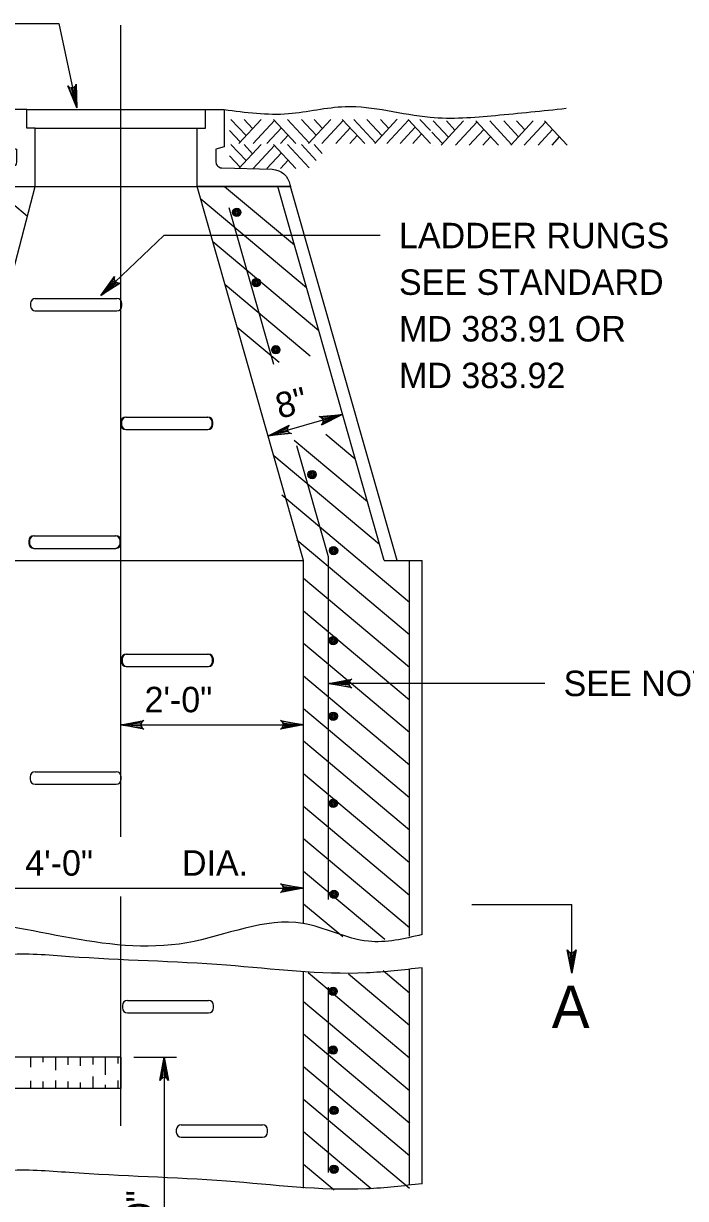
# Model space of a CAD drawing. Extents: x 0.2 to 7.1, y 1.2 to 11.2.
# Drawn here: x 1.727 to 3.289, y 5.546 to 8.317 of the extents above; entities that cross this region are included whole.
import ezdxf

# ---------------------------------------------------------------- set-up
doc = ezdxf.new("R2010")
doc.units = 0
for name, color, linetype in [('DETL-DIMS', 7, 'Continuous'), ('DETL-LINE', 7, 'Continuous'), ('DETL-NOTE', 7, 'Continuous'), ('DETL-PATT', 7, 'Continuous')]:
    doc.layers.add(name, color=color, linetype=linetype)

msp = doc.modelspace()

# ---------------------------------------------------------------- linework, layer by layer
at = {"layer": 'DETL-DIMS'}
for p, q in [((1.6294, 8.3172), (1.8102, 8.3172)), ((1.8102, 8.3172), (1.8527, 8.1187)), ((1.9564, 6.3991), (1.9564, 8.3133)), ((2.0583, 7.8172), (1.9094, 7.6754)), ((2.5686, 7.8172), (2.0583, 7.8172)), ((2.4798, 7.3951), (2.304, 7.3451)), ((2.957, 6.7604), (2.4466, 6.7604)), ((1.9564, 6.6633), (2.3878, 6.6633)), ((1.525, 6.2779), (2.3878, 6.2779)), ((1.9564, 5.7169), (1.9564, 6.2581)), ((2.7848, 6.2393), (3.0201, 6.2393)), ((3.0201, 6.0775), (3.0201, 6.2393)), ((1.9869, 5.879), (2.0881, 5.879)), ((2.0587, 5.879), (2.0587, 5.1333))]:
    msp.add_line(p, q, dxfattribs=at)
for points in [[(1.8527, 8.1187), (1.8312, 8.1701), (1.8349, 8.1666), (1.839, 8.1652), (1.8427, 8.1654), (1.8462, 8.1668), (1.8493, 8.1697), (1.8513, 8.1744), (1.8527, 8.1187), (1.8493, 8.1697), (1.8462, 8.1668), (1.8527, 8.1187), (1.8427, 8.1654), (1.839, 8.1652), (1.8527, 8.1187), (1.8349, 8.1666)], [(1.9094, 7.6754), (1.942, 7.7206), (1.941, 7.7156), (1.9419, 7.7114), (1.944, 7.7083), (1.947, 7.7061), (1.9511, 7.7049), (1.9562, 7.7057), (1.9094, 7.6754), (1.9511, 7.7049), (1.947, 7.7061), (1.9094, 7.6754), (1.944, 7.7083), (1.9419, 7.7114), (1.9094, 7.6754), (1.941, 7.7156)], [(2.4798, 7.3951), (2.4298, 7.3702), (2.4331, 7.3742), (2.4342, 7.3783), (2.4338, 7.382), (2.4322, 7.3854), (2.4291, 7.3883), (2.4242, 7.39), (2.4798, 7.3951), (2.4291, 7.3883), (2.4322, 7.3854), (2.4798, 7.3951), (2.4338, 7.382), (2.4342, 7.3783), (2.4798, 7.3951), (2.4331, 7.3742)], [(2.304, 7.3451), (2.3539, 7.37), (2.3506, 7.366), (2.3496, 7.3619), (2.35, 7.3582), (2.3516, 7.3548), (2.3547, 7.3519), (2.3595, 7.3502), (2.304, 7.3451), (2.3547, 7.3519), (2.3516, 7.3548), (2.304, 7.3451), (2.35, 7.3582), (2.3496, 7.3619), (2.304, 7.3451), (2.3506, 7.366)], [(2.4466, 6.7604), (2.5014, 6.7706), (2.4972, 6.7677), (2.495, 6.764), (2.4944, 6.7604), (2.495, 6.7567), (2.4972, 6.753), (2.5014, 6.7501), (2.4466, 6.7604), (2.4972, 6.753), (2.495, 6.7567), (2.4466, 6.7604), (2.4944, 6.7604), (2.495, 6.764), (2.4466, 6.7604), (2.4972, 6.7677)], [(1.9564, 6.6633), (2.0112, 6.6736), (2.007, 6.6706), (2.0048, 6.667), (2.0042, 6.6633), (2.0048, 6.6596), (2.007, 6.6559), (2.0112, 6.653), (1.9564, 6.6633), (2.007, 6.6559), (2.0048, 6.6596), (1.9564, 6.6633), (2.0042, 6.6633), (2.0048, 6.667), (1.9564, 6.6633), (2.007, 6.6706)], [(2.3878, 6.6633), (2.3329, 6.653), (2.3372, 6.6559), (2.3393, 6.6596), (2.34, 6.6633), (2.3393, 6.667), (2.3372, 6.6706), (2.3329, 6.6736), (2.3878, 6.6633), (2.3372, 6.6706), (2.3393, 6.667), (2.3878, 6.6633), (2.34, 6.6633), (2.3393, 6.6596), (2.3878, 6.6633), (2.3372, 6.6559)], [(2.3878, 6.2779), (2.3329, 6.2677), (2.3372, 6.2706), (2.3393, 6.2743), (2.34, 6.2779), (2.3393, 6.2816), (2.3372, 6.2853), (2.3329, 6.2882), (2.3878, 6.2779), (2.3372, 6.2853), (2.3393, 6.2816), (2.3878, 6.2779), (2.34, 6.2779), (2.3393, 6.2743), (2.3878, 6.2779), (2.3372, 6.2706)], [(3.0201, 6.0775), (3.0098, 6.1324), (3.0128, 6.1281), (3.0164, 6.126), (3.0201, 6.1253), (3.0238, 6.126), (3.0275, 6.1281), (3.0304, 6.1324), (3.0201, 6.0775), (3.0275, 6.1281), (3.0238, 6.126), (3.0201, 6.0775), (3.0201, 6.1253), (3.0164, 6.126), (3.0201, 6.0775), (3.0128, 6.1281)], [(2.0587, 5.879), (2.069, 5.8242), (2.0661, 5.8284), (2.0624, 5.8306), (2.0587, 5.8313), (2.055, 5.8306), (2.0514, 5.8284), (2.0484, 5.8242), (2.0587, 5.879), (2.0514, 5.8284), (2.055, 5.8306), (2.0587, 5.879), (2.0587, 5.8313), (2.0624, 5.8306), (2.0587, 5.879), (2.0661, 5.8284)]]:
    msp.add_lwpolyline(points, dxfattribs=at)
at = {"layer": 'DETL-LINE'}
for p, q in [((1.7346, 8.1145), (2.1562, 8.1145)), ((1.7542, 8.0704), (2.1366, 8.0704)), ((1.525, 7.0508), (1.7542, 7.9331)), ((1.5336, 7.9331), (2.3572, 7.9331)), ((2.3878, 7.0508), (2.1366, 7.9331)), ((2.5778, 7.0508), (2.3266, 7.9331)), ((2.6084, 7.0508), (2.3572, 7.9331)), ((2.3174, 7.5127), (2.2122, 7.8822)), ((1.7437, 7.657), (1.7437, 7.6511)), ((1.7537, 7.6687), (1.9455, 7.6687)), ((1.7555, 7.6687), (1.9473, 7.6687)), ((1.9591, 7.6511), (1.9591, 7.657)), ((1.7537, 7.6393), (1.9455, 7.6393)), ((1.7555, 7.6393), (1.9473, 7.6393)), ((1.9565, 7.377), (1.9565, 7.3711)), ((1.9583, 7.377), (1.9583, 7.3711)), ((1.9683, 7.3887), (2.1601, 7.3887)), ((1.9701, 7.3887), (2.1619, 7.3887)), ((2.1718, 7.3711), (2.1718, 7.377)), ((2.1736, 7.3711), (2.1736, 7.377)), ((1.9683, 7.3593), (2.1601, 7.3593)), ((1.9701, 7.3593), (2.1619, 7.3593)), ((2.4466, 7.059), (2.372, 7.3209)), ((1.7394, 7.097), (1.7394, 7.0911)), ((1.7412, 7.097), (1.7412, 7.0911)), ((1.7512, 7.1088), (1.943, 7.1088)), ((1.753, 7.1088), (1.9448, 7.1088)), ((1.9548, 7.0911), (1.9548, 7.097)), ((1.9565, 7.0911), (1.9565, 7.097)), ((1.7512, 7.0793), (1.943, 7.0793)), ((1.753, 7.0793), (1.9448, 7.0793)), ((1.5642, 7.0508), (2.3878, 7.0508)), ((2.3878, 6.1946), (2.3878, 7.0508)), ((2.4466, 6.2507), (2.4466, 7.059)), ((2.5774, 7.0508), (2.6672, 7.0508)), ((2.6378, 6.1647), (2.6378, 7.0508)), ((2.6672, 6.1684), (2.6672, 7.0508)), ((1.9578, 6.8183), (1.9578, 6.8124)), ((1.9596, 6.8183), (1.9596, 6.8124)), ((1.9695, 6.83), (2.1613, 6.83)), ((1.9713, 6.83), (2.1631, 6.83)), ((2.1731, 6.8124), (2.1731, 6.8183)), ((2.1749, 6.8124), (2.1749, 6.8183)), ((1.9695, 6.8006), (2.1613, 6.8006)), ((1.9713, 6.8006), (2.1631, 6.8006)), ((1.7423, 6.5407), (1.7423, 6.5348)), ((1.7541, 6.5525), (1.9459, 6.5525)), ((1.9576, 6.5348), (1.9576, 6.5407)), ((1.7541, 6.5231), (1.9459, 6.5231)), ((2.3878, 5.5702), (2.3878, 6.0795)), ((2.6378, 5.578), (2.6378, 6.0873)), ((2.6672, 5.5807), (2.6672, 6.09)), ((2.4466, 5.6071), (2.4466, 6.0441)), ((1.9601, 6.0013), (1.9601, 5.9954)), ((1.9719, 6.013), (2.1636, 6.013)), ((2.1754, 5.9954), (2.1754, 6.0013)), ((1.9719, 5.9836), (2.1636, 5.9836)), ((1.9575, 5.879), (1.4624, 5.879)), ((1.9575, 5.8055), (1.9575, 5.879)), ((1.9575, 5.8055), (1.4624, 5.8055)), ((2.0992, 5.7199), (2.291, 5.7199)), ((2.0874, 5.7082), (2.0874, 5.7023)), ((2.0992, 5.6905), (2.291, 5.6905)), ((2.3027, 5.7023), (2.3027, 5.7082))]:
    msp.add_line(p, q, dxfattribs=at)
for points in [[(1.6905, 8.1145), (1.6905, 8.0263), (1.7101, 8.0206), (1.7101, 7.9915), (1.7094, 7.9858), (1.7073, 7.9827), (1.7053, 7.981), (1.7028, 7.9789), (1.6994, 7.9771), (1.6958, 7.9768), (1.5775, 7.9733), (1.5693, 7.9723), (1.5614, 7.9695), (1.5551, 7.9667), (1.5496, 7.9626), (1.5444, 7.9574), (1.5409, 7.9518), (1.5371, 7.9435), (1.5357, 7.9379), (1.5336, 7.9331), (1.7542, 7.9331), (1.7542, 8.0704), (1.7346, 8.0704), (1.7346, 8.1145)], [(2.2003, 8.1145), (2.2003, 8.0263), (2.1807, 8.0206), (2.1807, 7.9915), (2.1814, 7.9858), (2.1835, 7.9827), (2.1856, 7.981), (2.188, 7.9789), (2.1914, 7.9771), (2.195, 7.9768), (2.3133, 7.9733), (2.3215, 7.9723), (2.3295, 7.9695), (2.3357, 7.9667), (2.3412, 7.9626), (2.3464, 7.9574), (2.3499, 7.9518), (2.3537, 7.9435), (2.3551, 7.9379), (2.3572, 7.9331), (2.1366, 7.9331), (2.1366, 8.0704), (2.1562, 8.0704), (2.1562, 8.1145)]]:
    msp.add_lwpolyline(points, close=True, dxfattribs=at)
for centre, radius in [((2.2301, 7.8719), 0.0098), ((2.2301, 7.8719), 0.00735), ((2.2301, 7.8719), 0.0049), ((2.2301, 7.8719), 0.00245), ((2.2759, 7.7063), 0.0098), ((2.2759, 7.7063), 0.00735), ((2.2759, 7.7063), 0.0049), ((2.2759, 7.7063), 0.00245), ((2.3222, 7.5476), 0.0098), ((2.3222, 7.5476), 0.00735), ((2.3222, 7.5476), 0.0049), ((2.3222, 7.5476), 0.00245), ((2.4077, 7.2533), 0.0098), ((2.4077, 7.2533), 0.00735), ((2.4077, 7.2533), 0.0049), ((2.4077, 7.2533), 0.00245), ((2.4583, 7.074), 0.0098), ((2.4583, 7.074), 0.00735), ((2.4583, 7.074), 0.0049), ((2.4583, 7.074), 0.00245), ((2.4573, 6.0344), 0.0098), ((2.4573, 6.0344), 0.00735), ((2.4573, 6.0344), 0.0049), ((2.4573, 6.0344), 0.00245), ((2.4573, 5.8959), 0.0098), ((2.4573, 5.8959), 0.00735), ((2.4573, 5.8959), 0.0049), ((2.4573, 5.8959), 0.00245), ((2.4592, 5.7535), 0.0098), ((2.4592, 5.7535), 0.00735), ((2.4592, 5.7535), 0.0049), ((2.4592, 5.7535), 0.00245), ((2.4592, 5.6149), 0.0098), ((2.4592, 5.6149), 0.00735), ((2.4592, 5.6149), 0.0049), ((2.4592, 5.6149), 0.00245)]:
    msp.add_circle(centre, radius, dxfattribs=at)
for centre, start, end in [((1.7555, 7.657), 90, 180), ((1.7555, 7.6511), 180, 270), ((1.9473, 7.657), 0, 90), ((1.9473, 7.6511), 270, 0), ((1.9683, 7.377), 90, 180), ((1.9701, 7.377), 90, 180), ((2.1601, 7.377), 0, 90), ((2.1619, 7.377), 0, 90), ((1.9683, 7.3711), 180, 270), ((1.9701, 7.3711), 180, 270), ((2.1601, 7.3711), 270, 0), ((2.1619, 7.3711), 270, 0), ((1.7512, 7.097), 90, 180), ((1.753, 7.097), 90, 180), ((1.943, 7.097), 0, 90), ((1.9448, 7.097), 0, 90), ((1.7512, 7.0911), 180, 270), ((1.753, 7.0911), 180, 270), ((1.943, 7.0911), 270, 0), ((1.9448, 7.0911), 270, 0), ((1.9695, 6.8183), 90, 180), ((1.9713, 6.8183), 90, 180), ((2.1613, 6.8183), 0, 90), ((2.1631, 6.8183), 0, 90), ((1.9695, 6.8124), 180, 270), ((1.9713, 6.8124), 180, 270), ((2.1613, 6.8124), 270, 0), ((2.1631, 6.8124), 270, 0), ((1.7541, 6.5407), 90, 180), ((1.9459, 6.5407), 0, 90), ((1.7541, 6.5348), 180, 270), ((1.9459, 6.5348), 270, 0), ((1.9719, 6.0013), 90, 180), ((1.9719, 5.9954), 180, 270), ((2.1636, 6.0013), 0, 90), ((2.1636, 5.9954), 270, 0), ((2.0992, 5.7082), 90, 180), ((2.291, 5.7082), 0, 90), ((2.0992, 5.7023), 180, 270), ((2.291, 5.7023), 270, 0)]:
    msp.add_arc(centre, 0.0118, start, end, dxfattribs=at)
for points in [[(2.2003, 8.1145), (2.3522, 8.1047), (2.4857, 8.1214), (2.6859, 8.0963), (2.8402, 8.1005), (3.0071, 8.1172)], [(2.6672, 6.1684), (2.5405, 6.1525), (2.386, 6.1946), (2.112, 6.149), (1.5326, 6.2052), (1.2456, 6.1684)], [(2.6672, 6.09), (2.5361, 6.0779), (2.2058, 6.096), (1.8352, 6.1162), (1.6841, 6.1202), (1.525, 6.09), (1.2456, 6.0699)], [(2.6672, 5.5807), (2.5361, 5.5686), (2.2058, 5.5867), (1.8352, 5.6069), (1.6841, 5.6109), (1.525, 5.5807), (1.2456, 5.5606)]]:
    msp.add_spline(points, degree=3, dxfattribs=at)
at = {"layer": 'DETL-PATT'}
for p, q in [((2.252, 8.053), (2.2163, 8.0912)), ((2.2347, 8.0343), (2.2874, 8.0912)), ((2.2672, 8.0695), (2.2474, 8.0912)), ((2.2686, 8.0343), (2.3192, 8.0885)), ((2.3011, 8.0343), (2.3354, 8.0712)), ((2.3697, 8.0343), (2.3167, 8.0912)), ((2.4008, 8.0359), (2.3496, 8.0912)), ((2.4171, 8.0536), (2.3824, 8.0912)), ((2.3994, 8.0343), (2.4521, 8.0912)), ((2.4319, 8.0702), (2.4128, 8.0912)), ((2.4309, 8.0343), (2.481, 8.0884)), ((2.4634, 8.0343), (2.4973, 8.0712)), ((2.5319, 8.0343), (2.4786, 8.0912)), ((2.5577, 8.0361), (2.5065, 8.0912)), ((2.5729, 8.0525), (2.5372, 8.0912)), ((2.556, 8.0343), (2.6086, 8.0914)), ((2.5888, 8.0696), (2.569, 8.0912)), ((2.5842, 8.0343), (2.6351, 8.0894)), ((2.6153, 8.0343), (2.6507, 8.073)), ((2.6867, 8.0343), (2.6341, 8.0912)), ((2.6867, 8.0647), (2.6623, 8.0912)), ((2.7294, 8.0493), (2.6937, 8.0875)), ((2.7121, 8.0306), (2.7647, 8.0875)), ((2.7446, 8.0658), (2.7248, 8.0875)), ((2.746, 8.0306), (2.7966, 8.0848)), ((2.7785, 8.0306), (2.8128, 8.0675)), ((2.8471, 8.0306), (2.7941, 8.0875)), ((2.8782, 8.0322), (2.8269, 8.0875)), ((2.8945, 8.0499), (2.8598, 8.0875)), ((2.8768, 8.0306), (2.9294, 8.0875)), ((2.9093, 8.0665), (2.8902, 8.0875)), ((2.9082, 8.0306), (2.9584, 8.0847)), ((2.9408, 8.0306), (2.9747, 8.0675)), ((3.0093, 8.0306), (2.956, 8.0875)), ((2.2379, 8.0378), (2.2128, 8.0647)), ((2.3333, 8.0343), (2.3513, 8.0539)), ((2.4966, 8.0343), (2.5139, 8.0534)), ((2.6454, 8.0343), (2.6659, 8.0567)), ((2.7153, 8.0341), (2.6902, 8.061)), ((2.8107, 8.0306), (2.8287, 8.0502)), ((2.974, 8.0306), (2.9913, 8.0497)), ((2.2161, 8.0343), (2.2161, 8.0343)), ((2.252, 7.9938), (2.2163, 8.0319)), ((2.2347, 7.975), (2.2874, 8.0319)), ((2.2672, 8.0102), (2.2474, 8.0319)), ((2.2686, 7.975), (2.3192, 8.0293)), ((2.3011, 7.975), (2.3354, 8.012)), ((2.3697, 7.975), (2.3167, 8.0319)), ((2.4008, 7.9766), (2.3496, 8.0319)), ((2.4171, 7.9943), (2.3824, 8.0319)), ((2.4319, 8.0109), (2.4128, 8.0319)), ((2.6935, 8.0306), (2.6935, 8.0306)), ((2.2379, 7.9786), (2.2128, 8.0054)), ((2.3333, 7.975), (2.3513, 7.9947)), ((2.2161, 7.975), (2.2161, 7.975)), ((1.6524, 7.9331), (1.736, 7.8629)), ((2.2014, 7.9331), (2.3659, 7.7952)), ((2.145, 7.9037), (2.3946, 7.6943)), ((2.1737, 7.8029), (2.4233, 7.5934)), ((2.2024, 7.702), (2.4033, 7.5334)), ((2.2311, 7.6011), (2.3298, 7.5183)), ((2.4405, 7.3486), (2.5095, 7.2907)), ((2.3658, 7.3345), (2.5382, 7.1898)), ((2.3173, 7.2984), (2.5669, 7.0889)), ((2.3361, 7.2058), (2.6378, 6.9527)), ((2.3716, 7.0992), (2.6378, 6.8759)), ((2.3878, 7.0089), (2.6378, 6.7991)), ((2.3878, 6.9321), (2.6378, 6.7223)), ((2.3878, 6.8553), (2.6378, 6.6455)), ((2.3878, 6.7785), (2.6378, 6.5688)), ((2.3878, 6.7017), (2.6378, 6.492)), ((2.3878, 6.625), (2.6378, 6.4152)), ((2.3878, 6.5482), (2.6378, 6.3384)), ((2.3878, 6.4714), (2.6378, 6.2616)), ((2.3878, 6.3946), (2.6378, 6.1848)), ((2.3878, 6.3178), (2.579, 6.1573)), ((2.3878, 6.241), (2.4799, 6.1637)), ((2.3983, 6.0786), (2.6378, 5.8777)), ((2.4935, 6.0755), (2.6378, 5.9544)), ((2.5756, 6.0834), (2.6378, 6.0312)), ((2.3878, 6.0106), (2.6378, 5.8009)), ((2.3878, 5.9339), (2.6386, 5.7234)), ((1.7434, 5.879), (1.7434, 5.8557)), ((1.7728, 5.879), (1.7728, 5.8677)), ((1.8022, 5.879), (1.8022, 5.8483)), ((1.8316, 5.879), (1.8316, 5.8612)), ((1.861, 5.879), (1.861, 5.8585)), ((1.8904, 5.879), (1.8904, 5.8621)), ((1.9198, 5.879), (1.9198, 5.8372)), ((1.9493, 5.879), (1.9493, 5.864)), ((2.3878, 5.8571), (2.6378, 5.6473)), ((1.7434, 5.8233), (1.7434, 5.8055)), ((1.7728, 5.8215), (1.7728, 5.8055)), ((1.8022, 5.8243), (1.8022, 5.8055)), ((1.8316, 5.8215), (1.8316, 5.8055)), ((1.8904, 5.8335), (1.8904, 5.8055)), ((1.9493, 5.8243), (1.9493, 5.8055)), ((1.861, 5.8196), (1.861, 5.8055)), ((1.9198, 5.8141), (1.9198, 5.8055)), ((2.3878, 5.7803), (2.6378, 5.5705)), ((2.3878, 5.7035), (2.5473, 5.5696)), ((2.3878, 5.6267), (2.4599, 5.5662))]:
    msp.add_line(p, q, dxfattribs=at)
for centre, radius in [((2.4577, 6.8617), 0.0098), ((2.4577, 6.8617), 0.00735), ((2.4577, 6.8617), 0.0049), ((2.4577, 6.8617), 0.00245), ((2.4577, 6.6833), 0.0098), ((2.4577, 6.6833), 0.00735), ((2.4577, 6.6833), 0.0049), ((2.4577, 6.6833), 0.00245), ((2.4577, 6.4778), 0.0098), ((2.4577, 6.4778), 0.00735), ((2.4577, 6.4778), 0.0049), ((2.4577, 6.4778), 0.00245), ((2.4595, 6.2634), 0.0098), ((2.4595, 6.2634), 0.00735), ((2.4595, 6.2634), 0.0049), ((2.4595, 6.2634), 0.00245)]:
    msp.add_circle(centre, radius, dxfattribs=at)

# ---------------------------------------------------------------- texts
at = {"layer": 'DETL-NOTE'}
for s, height, p in [('LADDER RUNGS', 0.06, (2.6128, 7.7872)), ('SEE STANDARD', 0.06, (2.6128, 7.6772)), ('MD 383.91 OR', 0.06, (2.6128, 7.5672)), ('MD 383.92', 0.06, (2.6128, 7.4572)), ('SEE NOTE 1', 0.06, (3.0011, 6.7308)), ('2\'-0"', 0.06, (2.0125, 6.6927)), ('4\'-0"', 0.06, (1.7311, 6.3073)), ('DIA.', 0.06, (2.1008, 6.3073)), ('A', 0.1, (2.9732, 5.9481))]:
    msp.add_text(s, height=height, dxfattribs=at).set_placement(p)
for s, rotation, p in [('8"', 14.7479, (2.331, 7.3845)), ('6\'-0"', 90, (2.0293, 5.4054))]:
    msp.add_text(s, height=0.06, rotation=rotation, dxfattribs=at).set_placement(p)

doc.saveas('drawing.dxf')
